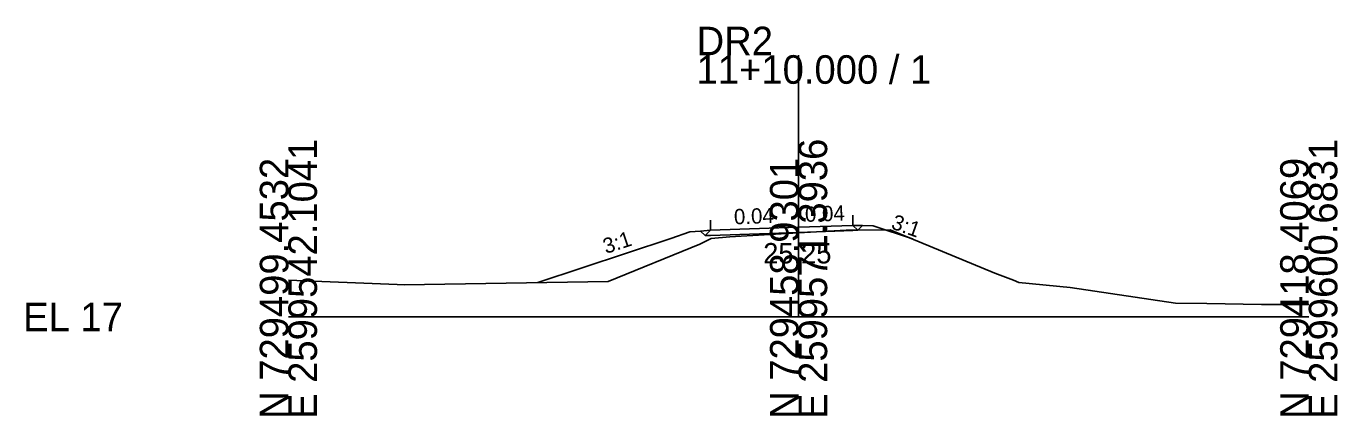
# Model space of a CAD drawing. Extents: x -26 to 1162, y -10 to 9515.
# Drawn here: x -25.7 to 102.8, y 5490.3 to 5528.5 of the extents above; entities that cross this region are included whole.
import ezdxf

# ---------------------------------------------------------------- set-up
doc = ezdxf.new("R2010")
doc.units = 0
for name, color, linetype in [('Exist Cross Section Cell', 7, 'Continuous'), ('Exist XS Center Line Elevation Label', 7, 'Continuous'), ('Exist XS Ground Line', 7, 'Continuous'), ('Prop XS Dump Level', 7, 'Continuous'), ('Prop XS EOT Tick Mark', 7, 'Continuous'), ('Prop XS Finish Grade', 7, 'Continuous'), ('Prop XS Finish Grade Earthwork', 7, 'Continuous'), ('Prop XS Finish Grade Pavement', 7, 'Continuous'), ('Prop XS Pvmt Edge Slope', 7, 'Continuous'), ('Prop XS SE Text', 7, 'Continuous'), ('Prop XS Side Slope Text', 7, 'Continuous'), ('Prop XS Subgrade Earthwork', 7, 'Continuous')]:
    doc.layers.add(name, color=color, linetype=linetype)

msp = doc.modelspace()

# ---------------------------------------------------------------- linework, layer by layer
at = {"layer": 'Exist Cross Section Cell'}
for p, q in [((50, 5500), (50, 5525.67)), ((0, 5500), (50, 5500)), ((50, 5500), (100, 5500))]:
    msp.add_line(p, q, dxfattribs=at)
at = {"layer": 'Exist XS Ground Line'}
msp.add_lwpolyline([(0, 5503.61), (10.66, 5503.17), (11.35, 5503.16), (31.34, 5503.48), (40.32, 5507.13), (41.44, 5507.71), (43.26, 5507.86), (50, 5508.25), (54.65, 5508.52), (58.96, 5508.56), (69.24, 5504.31), (71.06, 5503.61), (71.59, 5503.37), (76.6, 5502.9), (86.93, 5501.35), (90, 5501.32), (95.36, 5501.21), (100, 5501.22)], dxfattribs=at)
at = {"layer": 'Prop XS Dump Level'}
for p, q in [((50, 5508.8), (55.31, 5508.98)), ((41.36, 5508.5), (50, 5508.8))]:
    msp.add_line(p, q, dxfattribs=at)
at = {"layer": 'Prop XS EOT Tick Mark'}
for p, q in [((41.36, 5508.5), (41.36, 5509.5)), ((55.31, 5508.98), (55.31, 5509.98))]:
    msp.add_line(p, q, dxfattribs=at)
at = {"layer": 'Prop XS Finish Grade'}
for p, q in [((55.31, 5508.98), (56.26, 5508.96)), ((41.36, 5508.5), (40.39, 5508.42))]:
    msp.add_line(p, q, dxfattribs=at)
at = {"layer": 'Prop XS Finish Grade Earthwork'}
for p, q in [((56.26, 5508.96), (57.32, 5508.93)), ((57.32, 5508.93), (61.17, 5507.65)), ((37.47, 5507.71), (24.44, 5503.37)), ((39.35, 5508.34), (37.47, 5507.71)), ((40.39, 5508.42), (39.35, 5508.34))]:
    msp.add_line(p, q, dxfattribs=at)
at = {"layer": 'Prop XS Finish Grade Pavement'}
for p, q in [((50, 5508.8), (55.31, 5508.98)), ((41.36, 5508.5), (50, 5508.8))]:
    msp.add_line(p, q, dxfattribs=at)
at = {"layer": 'Prop XS Pvmt Edge Slope'}
for p, q in [((55.31, 5508.98), (55.79, 5508.5)), ((55.79, 5508.5), (56.26, 5508.96)), ((40.84, 5507.98), (40.39, 5508.42)), ((41.36, 5508.5), (40.84, 5507.98))]:
    msp.add_line(p, q, dxfattribs=at)
at = {"layer": 'Prop XS Subgrade Earthwork'}
for p, q in [((55.79, 5508.5), (56.26, 5508.96)), ((40.84, 5507.98), (40.39, 5508.42)), ((41.36, 5508), (40.84, 5507.98)), ((50, 5508.3), (41.36, 5508)), ((55.31, 5508.48), (50, 5508.3)), ((55.31, 5508.48), (55.79, 5508.5))]:
    msp.add_line(p, q, dxfattribs=at)

# ---------------------------------------------------------------- texts
at = {"layer": 'Exist Cross Section Cell'}
for s, p in [('DR2', (40, 5525.67)), ('11+10.000 / 1', (40, 5522.87)), ('EL 17', (-26, 5498.6))]:
    msp.add_text(s, height=2.8, dxfattribs=at).set_placement(p)
for s, p in [('E 2599542.1041', (2.8, 5490)), ('E 2599571.3936', (52.8, 5490)), ('E 2599600.6831', (102.8, 5490)), ('N 729499.4532', (0, 5490)), ('N 729458.9301', (50, 5490)), ('N 729418.4069', (100, 5490))]:
    msp.add_text(s, height=2.8, rotation=90, dxfattribs=at).set_placement(p)
at = {"layer": 'Exist XS Center Line Elevation Label'}
msp.add_text('25.25', height=2, dxfattribs=at).set_placement((46.53, 5505.25))
at = {"layer": 'Prop XS Dump Level'}
for p in [(57.32, 5508.89), (39.35, 5508.3)]:
    msp.add_text('Case1', height=0.04, dxfattribs=at).set_placement(p)
at = {"layer": 'Prop XS SE Text'}
for p in [(43.69, 5509.08), (50.65, 5509.32)]:
    msp.add_text('0.04', height=1.5, rotation=1.9749, dxfattribs=at).set_placement(p)
at = {"layer": 'Prop XS Side Slope Text'}
for rotation, p in [(340.3993, (58.98, 5508.7)), (18.1082, (31.12, 5506.17))]:
    msp.add_text('3:1', height=1.5, rotation=rotation, dxfattribs=at).set_placement(p)

doc.saveas('drawing.dxf')
